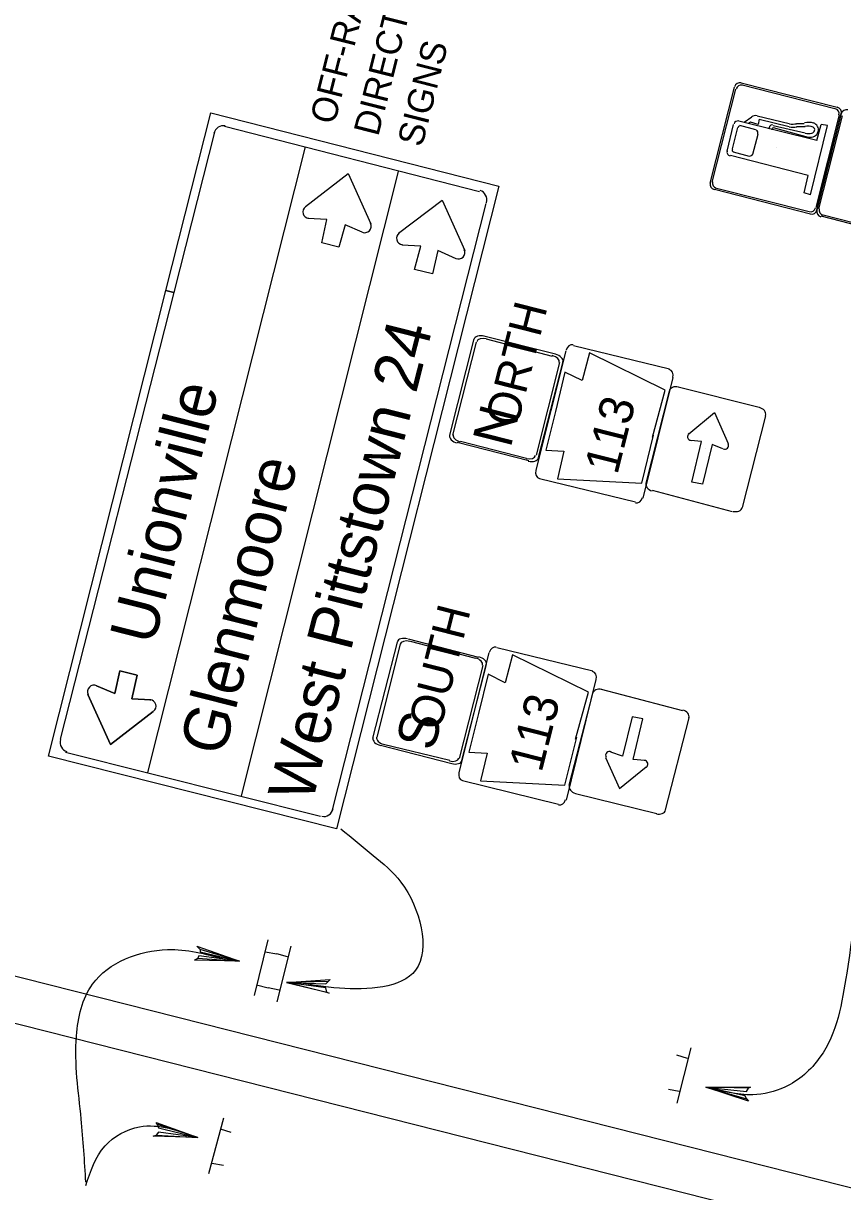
# Model space of a CAD drawing. Extents: x 640994 to 644422, y 298458 to 299646.
# Drawn here: x 643138.7 to 643234.7, y 299430.9 to 299567.7 of the extents above; entities that cross this region are included whole.
import ezdxf

# ---------------------------------------------------------------- set-up
doc = ezdxf.new("R2010")
doc.units = 0
doc.layers.add('2', color=7, linetype='Continuous')

msp = doc.modelspace()

# ---------------------------------------------------------------- linework, layer by layer
at = {"layer": '2'}
for p, q in [((643219.19, 299549), (643222.06, 299560.25)), ((643222.81, 299560.75), (643234.06, 299557.88)), ((643222.94, 299560.5), (643233.81, 299557.75)), ((643219.44, 299549.13), (643222.19, 299560)), ((643155.44, 299536.43), (643160.69, 299557.25)), ((643160.69, 299557.25), (643194.44, 299548.63)), ((643231.69, 299554), (643222.56, 299556.25)), ((643223.19, 299556.13), (643224.06, 299556.75)), ((643223.94, 299556.13), (643223.69, 299556)), ((643224.81, 299555.88), (643223.94, 299556.13)), ((643224.69, 299556.88), (643228.44, 299556)), ((643224.94, 299556.5), (643224.81, 299555.88)), ((643224.94, 299556.5), (643228.44, 299555.63)), ((643234.31, 299557), (643231.56, 299546.13)), ((643234.56, 299557.13), (643231.69, 299545.88)), ((643231.69, 299545.88), (643234.56, 299557.13)), ((643231.94, 299546), (643234.69, 299556.88)), ((643161.19, 299555.13), (643156.37, 299536.19)), ((643192.19, 299548), (643162.31, 299555.63)), ((643221.19, 299552.75), (643221.94, 299555.88)), ((643221.81, 299553), (643222.44, 299555.5)), ((643224.56, 299555.25), (643222.69, 299555.75)), ((643224.19, 299552.38), (643224.81, 299554.75)), ((643226.06, 299555.38), (643226.19, 299555.63)), ((643226.44, 299555.25), (643226.44, 299555.38)), ((643226.56, 299555.75), (643230.31, 299554.88)), ((643226.56, 299555.5), (643230.69, 299554.38)), ((643229.31, 299556), (643230.19, 299556)), ((643229.31, 299555.63), (643230.31, 299555.63)), ((643230.94, 299547.63), (643232.94, 299555.75)), ((643231.69, 299554), (643232.19, 299555.88)), ((643232.94, 299555.75), (643232.19, 299555.88)), ((643153.31, 299480), (643171.81, 299553.25)), ((643230.69, 299549.88), (643221.56, 299552.25)), ((643223.81, 299552.13), (643221.94, 299552.63)), ((643226.94, 299553.13), (643226.94, 299553.13)), ((643164.31, 299477.25), (643182.69, 299550.38)), ((643171.81, 299546.25), (643176.81, 299550.13)), ((643176.81, 299550.13), (643179.44, 299544.25)), ((643230.19, 299547.88), (643230.69, 299549.88)), ((643194.44, 299548.63), (643175.44, 299473.38)), ((643230.94, 299545.38), (643219.69, 299548.25)), ((643230.81, 299545.63), (643219.94, 299548.38)), ((643230.94, 299547.63), (643230.19, 299547.88)), ((643174.94, 299475.63), (643192.94, 299546.63)), ((643182.69, 299543.13), (643187.81, 299547)), ((643187.81, 299547), (643190.44, 299541.13)), ((643243.44, 299542.25), (643232.19, 299545.13)), ((643243.31, 299542.5), (643232.44, 299545.25)), ((643174.31, 299544.75), (643172.06, 299544.88)), ((643173.69, 299542), (643174.31, 299544.75)), ((643176.44, 299544.13), (643175.69, 299541.5)), ((643178.44, 299543.25), (643176.44, 299544.13)), ((643175.69, 299541.5), (643173.69, 299542)), ((643185.31, 299541.63), (643183.06, 299541.75)), ((643184.56, 299538.88), (643185.31, 299541.63)), ((643187.31, 299541.13), (643186.69, 299538.38)), ((643189.44, 299540.13), (643187.31, 299541.13)), ((643186.69, 299538.38), (643184.56, 299538.88)), ((643141.69, 299481.88), (643155.44, 299536.43)), ((643156.37, 299536.19), (643143.06, 299483.88)), ((643156.37, 299536.19), (643155.44, 299536.43)), ((643155.44, 299536.43), (643156.37, 299536.19)), ((643188.69, 299519.5), (643191.56, 299530.75)), ((643189.06, 299519.5), (643191.81, 299530.38)), ((643192.69, 299531.13), (643201.06, 299529)), ((643192.94, 299530.75), (643200.69, 299528.75)), ((643198.81, 299515.38), (643202.31, 299529.38)), ((643203.19, 299530), (643214.44, 299527.25)), ((643205.06, 299529.13), (643204.19, 299525.88)), ((643213.94, 299524.75), (643205.06, 299529.13)), ((643201.56, 299528), (643198.81, 299517.13)), ((643201.94, 299528.13), (643199.06, 299516.88)), ((643202.19, 299526.88), (643201.06, 299522.25)), ((643204.19, 299525.88), (643202.19, 299526.88)), ((643214.81, 299526.25), (643211.31, 299512.13)), ((643211.69, 299513.88), (643214.44, 299524.63)), ((643211.69, 299513.88), (643214.44, 299524.63)), ((643211.69, 299513.88), (643214.44, 299524.63)), ((643212.44, 299519.25), (643213.94, 299524.75)), ((643215.44, 299525.13), (643224.94, 299522.75)), ((643215.44, 299525.13), (643224.94, 299522.75)), ((643215.44, 299525.13), (643224.94, 299522.75)), ((643195.31, 299523.75), (643195.31, 299523.75)), ((643201.06, 299522.25), (643199.94, 299517.75)), ((643216.69, 299519.63), (643219.69, 299522.13)), ((643219.69, 299522.13), (643221.31, 299518.5)), ((643225.69, 299521.75), (643222.94, 299511)), ((643225.69, 299521.75), (643222.94, 299511)), ((643225.69, 299521.75), (643222.94, 299511)), ((643211.19, 299513.88), (643212.56, 299519.5)), ((643197.94, 299516.5), (643189.56, 299518.63)), ((643197.69, 299516.75), (643189.94, 299518.75)), ((643199.94, 299517.75), (643202.06, 299517.63)), ((643218.19, 299518.75), (643216.94, 299518.88)), ((643217.06, 299514), (643218.19, 299518.75)), ((643219.44, 299518.38), (643218.31, 299513.75)), ((643218.69, 299517.88), (643218.69, 299517.88)), ((643218.69, 299517.88), (643218.69, 299517.88)), ((643218.69, 299517.88), (643218.69, 299517.88)), ((643220.69, 299517.88), (643219.44, 299518.38)), ((643202.06, 299517.63), (643201.31, 299514.38)), ((643210.44, 299511.63), (643199.19, 299514.38)), ((643201.31, 299514.38), (643211.19, 299513.88)), ((643218.31, 299513.75), (643217.06, 299514)), ((643161.56, 299512.38), (643161.56, 299512.38)), ((643221.81, 299510.5), (643212.44, 299513)), ((643221.81, 299510.5), (643212.44, 299513)), ((643221.81, 299510.5), (643212.44, 299513)), ((643210.44, 299511.63), (643210.44, 299511.63)), ((643172.44, 299509.63), (643172.44, 299509.63)), ((643172.44, 299509.63), (643172.44, 299509.63)), ((643172.31, 299506.75), (643172.31, 299506.75)), ((643183.19, 299504), (643183.19, 299504)), ((643183.19, 299504), (643183.19, 299504)), ((643179.69, 299484), (643182.56, 299495.25)), ((643180.19, 299484.13), (643182.94, 299495)), ((643183.81, 299495.63), (643192.06, 299493.5)), ((643184.06, 299495.38), (643191.69, 299493.38)), ((643194.19, 299494.63), (643205.44, 299491.88)), ((643189.81, 299480), (643193.31, 299494)), ((643196.06, 299493.75), (643195.19, 299490.5)), ((643204.94, 299489.38), (643196.06, 299493.75)), ((643149.44, 299489.25), (643150.06, 299491.88)), ((643150.06, 299491.88), (643149.44, 299489.25)), ((643150.06, 299491.88), (643152.06, 299491.38)), ((643152.06, 299491.38), (643150.06, 299491.88)), ((643192.56, 299492.5), (643189.81, 299481.63)), ((643192.94, 299492.63), (643190.06, 299481.38)), ((643152.06, 299491.38), (643151.44, 299488.63)), ((643151.44, 299488.63), (643152.06, 299491.38)), ((643193.19, 299491.5), (643192.06, 299486.88)), ((643195.19, 299490.5), (643193.19, 299491.5)), ((643205.81, 299490.88), (643202.31, 299476.75)), ((643148.94, 299483.25), (643146.31, 299489.13)), ((643146.31, 299489.13), (643148.94, 299483.25)), ((643147.31, 299490.13), (643149.44, 299489.25)), ((643149.44, 299489.25), (643147.31, 299490.13)), ((643202.69, 299478.5), (643205.44, 299489.25)), ((643202.69, 299478.5), (643205.44, 299489.25)), ((643202.69, 299478.5), (643205.44, 299489.25)), ((643203.44, 299483.88), (643204.94, 299489.38)), ((643206.44, 299489.75), (643215.94, 299487.25)), ((643206.44, 299489.75), (643215.94, 299487.25)), ((643206.44, 299489.75), (643215.94, 299487.25)), ((643151.44, 299488.63), (643153.69, 299488.5)), ((643153.69, 299488.5), (643151.44, 299488.63)), ((643153.56, 299488.5), (643153.69, 299488.5)), ((643186.31, 299488.38), (643186.31, 299488.38)), ((643153.94, 299487.13), (643148.94, 299483.25)), ((643148.94, 299483.25), (643153.94, 299487.13)), ((643192.06, 299486.88), (643190.94, 299482.38)), ((643210.06, 299486.5), (643208.94, 299481.88)), ((643211.31, 299486.25), (643210.06, 299486.5)), ((643216.69, 299486.38), (643213.94, 299475.63)), ((643216.69, 299486.38), (643213.94, 299475.63)), ((643216.69, 299486.38), (643213.94, 299475.63)), ((643197.81, 299485.38), (643197.81, 299485.38)), ((643197.81, 299485.38), (643197.81, 299485.38)), ((643210.19, 299481.5), (643211.31, 299486.25)), ((643202.19, 299478.5), (643203.56, 299484.13)), ((643143.69, 299482.38), (643173.56, 299474.88)), ((643188.94, 299481), (643180.56, 299483.13)), ((643188.69, 299481.38), (643180.94, 299483.25)), ((643190.94, 299482.38), (643193.06, 299482.25)), ((643193.06, 299482.25), (643192.31, 299479)), ((643208.94, 299481.88), (643207.56, 299482.38)), ((643209.69, 299482.38), (643209.69, 299482.38)), ((643209.69, 299482.38), (643209.69, 299482.38)), ((643175.44, 299473.38), (643141.69, 299481.88)), ((643206.94, 299481.75), (643208.56, 299478.13)), ((643211.56, 299481.38), (643210.19, 299481.5)), ((643208.56, 299478.13), (643211.69, 299480.63)), ((643201.44, 299476.25), (643190.19, 299479)), ((643192.31, 299479), (643202.19, 299478.5)), ((643212.94, 299475.13), (643203.44, 299477.5)), ((643212.94, 299475.13), (643203.44, 299477.5)), ((643212.94, 299475.13), (643203.44, 299477.5)), ((643201.44, 299476.25), (643201.44, 299476.25)), ((643244.81, 299429), (643099.31, 299465.88)), ((643165.81, 299453.88), (643167.44, 299460.38)), ((643167.06, 299459), (643168.44, 299458.75)), ((643170.06, 299459.63), (643168.44, 299453.13)), ((643169.69, 299458.38), (643168.44, 299458.75)), ((643284.81, 299413.38), (643110.81, 299457.38)), ((643166.06, 299455.13), (643167.44, 299454.75)), ((643168.69, 299454.5), (643167.44, 299454.75)), ((643216.94, 299447.75), (643215.31, 299441.25)), ((643216.56, 299446.5), (643215.31, 299446.88)), ((643215.56, 299442.63), (643214.31, 299442.88)), ((643162.19, 299439.5), (643160.44, 299433)), ((643161.81, 299438.25), (643163.06, 299437.88)), ((643160.81, 299434.25), (643162.19, 299434))]:
    msp.add_line(p, q, dxfattribs=at)
for points in [[(643159.44, 299459.25), (643159.44, 299459), (643164.06, 299457.88), (643159.44, 299459.25), (643159.06, 299459.63), (643164.06, 299457.88), (643159.31, 299458.5), (643159.19, 299458.25), (643164.06, 299457.88), (643158.81, 299458), (643159.19, 299458.25)], [(643174.31, 299454.25), (643174.19, 299454.75), (643169.56, 299455.38), (643174.31, 299454.25), (643174.56, 299454.13), (643169.56, 299455.38), (643174.19, 299455.25), (643174.44, 299455.5), (643169.56, 299455.38), (643174.69, 299455.75), (643174.44, 299455.5)], [(643223.44, 299441.75), (643223.31, 299442.13), (643218.69, 299443.13), (643223.44, 299441.75), (643223.69, 299441.5), (643218.69, 299443.13), (643223.44, 299442.63), (643223.69, 299443), (643218.69, 299443.13), (643223.94, 299443.13), (643223.69, 299443)], [(643154.44, 299438.75), (643154.56, 299438.38), (643159.19, 299437.25), (643154.44, 299438.75), (643154.31, 299439), (643159.19, 299437.25), (643154.56, 299437.88), (643154.31, 299437.5), (643159.19, 299437.25), (643153.94, 299437.38), (643154.31, 299437.5)]]:
    msp.add_lwpolyline(points, dxfattribs=at)
for centre, radius, start, end in [((643222.68, 299560.12), 0.645, 75.7754, 165.7754), ((643222.82, 299559.89), 0.597, 75.7754, 165.7754), ((643233.7, 299557.13), 0.597, 345.7754, 75.7754), ((643233.93, 299557.27), 0.645, 345.7754, 75.7754), ((643235.18, 299556.95), 0.645, 75.7754, 165.7754), ((643222.46, 299555.8), 0.486, 83.6778, 164.7031), ((643224.57, 299555.92), 0.991, 81.3158, 122.9841), ((643230.77, 299553.42), 2.68, 78.1727, 101.1253), ((643231.04, 299555.25), 0.84, 344.9893, 71.1198), ((643222.7, 299555.43), 0.274, 92.8615, 169.1523), ((643224.4, 299554.88), 0.392, 341.4902, 59.3145), ((643226.45, 299555.5), 0.318, 75.201, 153.6335), ((643226.53, 299555.37), 0.0771, 64.9719, 167.615), ((643228.89, 299558.9), 3.35, 262.3862, 278.0519), ((643228.89, 299558.9), 2.98, 262.3862, 278.0519), ((643230.66, 299554.09), 1.59, 68.02, 103.4387), ((643230.69, 299556.33), 1.53, 256.8807, 285.2561), ((643230.95, 299555.32), 0.953, 254.9902, 342.4176), ((643231.06, 299555.24), 0.381, 275.7441, 58.872), ((643221.58, 299552.63), 0.415, 157.4008, 262.3628), ((643222.02, 299552.88), 0.249, 154.0614, 244.0323), ((643223.87, 299552.49), 0.314, 262.0164, 342.4308), ((643219.83, 299548.87), 0.645, 165.7754, 255.7754), ((643220.06, 299549.01), 0.597, 165.7754, 255.7754), ((643172.22, 299545.63), 0.745, 125.638, 266.3035), ((643230.94, 299546.25), 0.597, 255.7754, 345.7754), ((643231.08, 299546.02), 0.645, 255.7754, 345.7754), ((643232.33, 299545.7), 0.645, 165.7754, 255.7754), ((643232.56, 299545.84), 0.597, 165.7754, 255.7754), ((643178.75, 299543.94), 0.745, 244.0264, 27.9331), ((643183.19, 299542.56), 0.745, 125.638, 266.3035), ((643189.72, 299540.86), 0.745, 244.0264, 27.9331), ((643216.99, 299519.32), 0.45, 126.1169, 265.3481), ((643220.91, 299518.29), 0.45, 247.2918, 24.1455), ((643147.01, 299489.46), 0.745, 64.0264, 207.9331), ((643147.01, 299489.46), 0.745, 64.0264, 207.9331), ((643153.54, 299487.76), 0.745, 305.638, 86.3035), ((643153.54, 299487.76), 0.745, 305.638, 86.3035), ((643207.41, 299481.99), 0.46, 64.0256, 207.9322), ((643211.44, 299480.95), 0.46, 305.6371, 86.3026)]:
    msp.add_arc(centre, radius, start, end, dxfattribs=at)
for centre, major_axis, ratio, start_param, end_param in [((643162.09, 299554.54), (-0.29, -1.16), 0.890186, 3.141593, 4.712389), ((643191.96, 299546.97), (0.29, 1.16), 0.890186, 4.712389, 6.283185), ((643192.57, 299530.45), (-1.04, 0.26), 0.6, 4.712389, 6.283185), ((643192.83, 299530.19), (-0.964, 0.244), 0.6, 4.712389, 6.283185), ((643202.95, 299529.27), (-0.198, -0.782), 0.8, 3.141593, 4.712389), ((643200.55, 299528.23), (-0.964, 0.244), 0.6, 3.141593, 4.712389), ((643200.91, 299528.34), (-1.04, 0.26), 0.6, 3.141593, 4.712389), ((643214.21, 299526.41), (0.198, 0.782), 0.8, 4.712389, 6.283185), ((643215.3, 299524.43), (-0.903, 0.229), 0.769266, 4.712389, 6.283185), ((643215.3, 299524.43), (-0.903, 0.229), 0.769266, 4.712389, 6.283185), ((643215.3, 299524.43), (-0.903, 0.229), 0.769266, 4.712389, 6.283185), ((643224.78, 299522.03), (-0.903, 0.229), 0.769266, 3.141593, 4.712389), ((643224.78, 299522.03), (-0.903, 0.229), 0.769266, 3.141593, 4.712389), ((643224.78, 299522.03), (-0.903, 0.229), 0.769266, 3.141593, 4.712389), ((643189.72, 299519.2), (1.04, -0.26), 0.6, 3.141593, 4.712389), ((643190.07, 299519.3), (0.964, -0.244), 0.6, 3.141593, 4.712389), ((643197.79, 299517.35), (0.964, -0.244), 0.6, 4.712389, 6.283185), ((643198.05, 299517.08), (1.04, -0.26), 0.6, 4.712389, 6.283185), ((643199.39, 299515.2), (-0.198, -0.782), 0.8, 4.712389, 6.283185), ((643212.57, 299513.66), (0.903, -0.229), 0.769266, 3.141593, 4.712389), ((643212.57, 299513.66), (0.903, -0.229), 0.769266, 3.141593, 4.712389), ((643212.57, 299513.66), (0.903, -0.229), 0.769266, 3.141593, 4.712389), ((643210.64, 299512.35), (0.198, 0.782), 0.8, 3.141593, 4.712389), ((643222.05, 299511.26), (0.903, -0.229), 0.769266, 4.712389, 6.283185), ((643222.05, 299511.26), (0.903, -0.229), 0.769266, 4.712389, 6.283185), ((643222.05, 299511.26), (0.903, -0.229), 0.769266, 4.712389, 6.283185), ((643183.59, 299495.02), (-1.04, 0.26), 0.6, 4.712389, 6.283185), ((643183.85, 299494.76), (-0.964, 0.244), 0.6, 4.712389, 6.283185), ((643193.95, 299493.89), (-0.198, -0.782), 0.8, 3.141593, 4.712389), ((643191.57, 299492.8), (-0.964, 0.244), 0.6, 3.141593, 4.712389), ((643191.93, 299492.91), (-1.04, 0.26), 0.6, 3.141593, 4.712389), ((643205.21, 299491.04), (0.198, 0.782), 0.8, 4.712389, 6.283185), ((643206.32, 299489), (-0.903, 0.229), 0.769266, 4.712389, 6.283185), ((643206.32, 299489), (-0.903, 0.229), 0.769266, 4.712389, 6.283185), ((643206.32, 299489), (-0.903, 0.229), 0.769266, 4.712389, 6.283185), ((643215.8, 299486.6), (-0.903, 0.229), 0.769266, 3.141593, 4.712389), ((643215.8, 299486.6), (-0.903, 0.229), 0.769266, 3.141593, 4.712389), ((643215.8, 299486.6), (-0.903, 0.229), 0.769266, 3.141593, 4.712389), ((643144.13, 299483.59), (-0.29, -1.16), 0.890186, 4.712389, 6.283185), ((643180.74, 299483.77), (1.04, -0.26), 0.6, 3.141593, 4.712389), ((643181.09, 299483.87), (0.964, -0.244), 0.6, 3.141593, 4.712389), ((643188.81, 299481.92), (0.964, -0.244), 0.6, 4.712389, 6.283185), ((643189.08, 299481.65), (1.04, -0.26), 0.6, 4.712389, 6.283185), ((643190.39, 299479.82), (-0.198, -0.782), 0.8, 4.712389, 6.283185), ((643203.59, 299478.23), (0.903, -0.229), 0.769266, 3.141593, 4.712389), ((643203.59, 299478.23), (0.903, -0.229), 0.769266, 3.141593, 4.712389), ((643203.59, 299478.23), (0.903, -0.229), 0.769266, 3.141593, 4.712389), ((643201.64, 299476.97), (0.198, 0.782), 0.8, 3.141593, 4.712389), ((643174.01, 299476.02), (0.29, 1.16), 0.890186, 3.141593, 4.712389), ((643213.07, 299475.83), (0.903, -0.229), 0.769266, 4.712389, 6.283185), ((643213.07, 299475.83), (0.903, -0.229), 0.769266, 4.712389, 6.283185), ((643213.07, 299475.83), (0.903, -0.229), 0.769266, 4.712389, 6.283185)]:
    msp.add_ellipse(centre, major_axis=major_axis, ratio=ratio, start_param=start_param, end_param=end_param, dxfattribs=at)
for points in [[(643249.06, 299537.63), (643245.56, 299503.5), (643237.81, 299472.63), (643235.19, 299456.5), (643232.06, 299446.63), (643227.94, 299443.13), (643224.19, 299442.25), (643218.69, 299443.13)], [(643175.94, 299473.38), (643179.72, 299470.28), (643182.98, 299467.13), (643184.68, 299456.84), (643175.78, 299454.72), (643170.94, 299455.38)], [(643146.06, 299432), (643145.52, 299439.4), (643144.97, 299449.15), (643146.85, 299455.2), (643155.62, 299459.25), (643162.22, 299458.17)], [(643146.06, 299431.63), (643148.31, 299436.25), (643152.35, 299438.49), (643159.19, 299437.25)]]:
    msp.add_spline(points, degree=3, dxfattribs=at)

# ---------------------------------------------------------------- texts
for s, height, rotation, p in [('DIRECTIONAL', 3, 75.7789, (643180.31, 299554.38)), ('OFF-RAMP', 3, 75.7789, (643175.19, 299555.75)), ('SIGNS', 3, 75.7789, (643185.44, 299553.13)), ('ORTH', 3.875, 75.7783, (643196.56, 299520.25)), ('West Pittstown 24', 5.3752, 75.7788, (643172.56, 299476.25)), ('Unionville', 5.375, 75.7788, (643154.02, 299494.76)), ('113', 4, 75.7777, (643208.31, 299514.75)), ('N', 4.63, 75.7284, (643195.81, 299517.88)), ('Glenmoore   ', 5.3752, 75.7788, (643162.21, 299481.75)), ('OUTH', 3.875, 75.7783, (643187.56, 299484.75)), ('113', 4, 75.7777, (643199.44, 299479.88)), ('S', 4.63, 75.7284, (643186.81, 299482.38))]:
    msp.add_text(s, height=height, rotation=rotation, dxfattribs=at).set_placement(p)

doc.saveas('drawing.dxf')
